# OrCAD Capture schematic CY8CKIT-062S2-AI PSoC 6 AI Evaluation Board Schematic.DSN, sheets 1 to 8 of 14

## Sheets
1 01. Title Page: title: PSoC™ 6 AI Evaluation Board; rev: 03; note: 630-60699-01
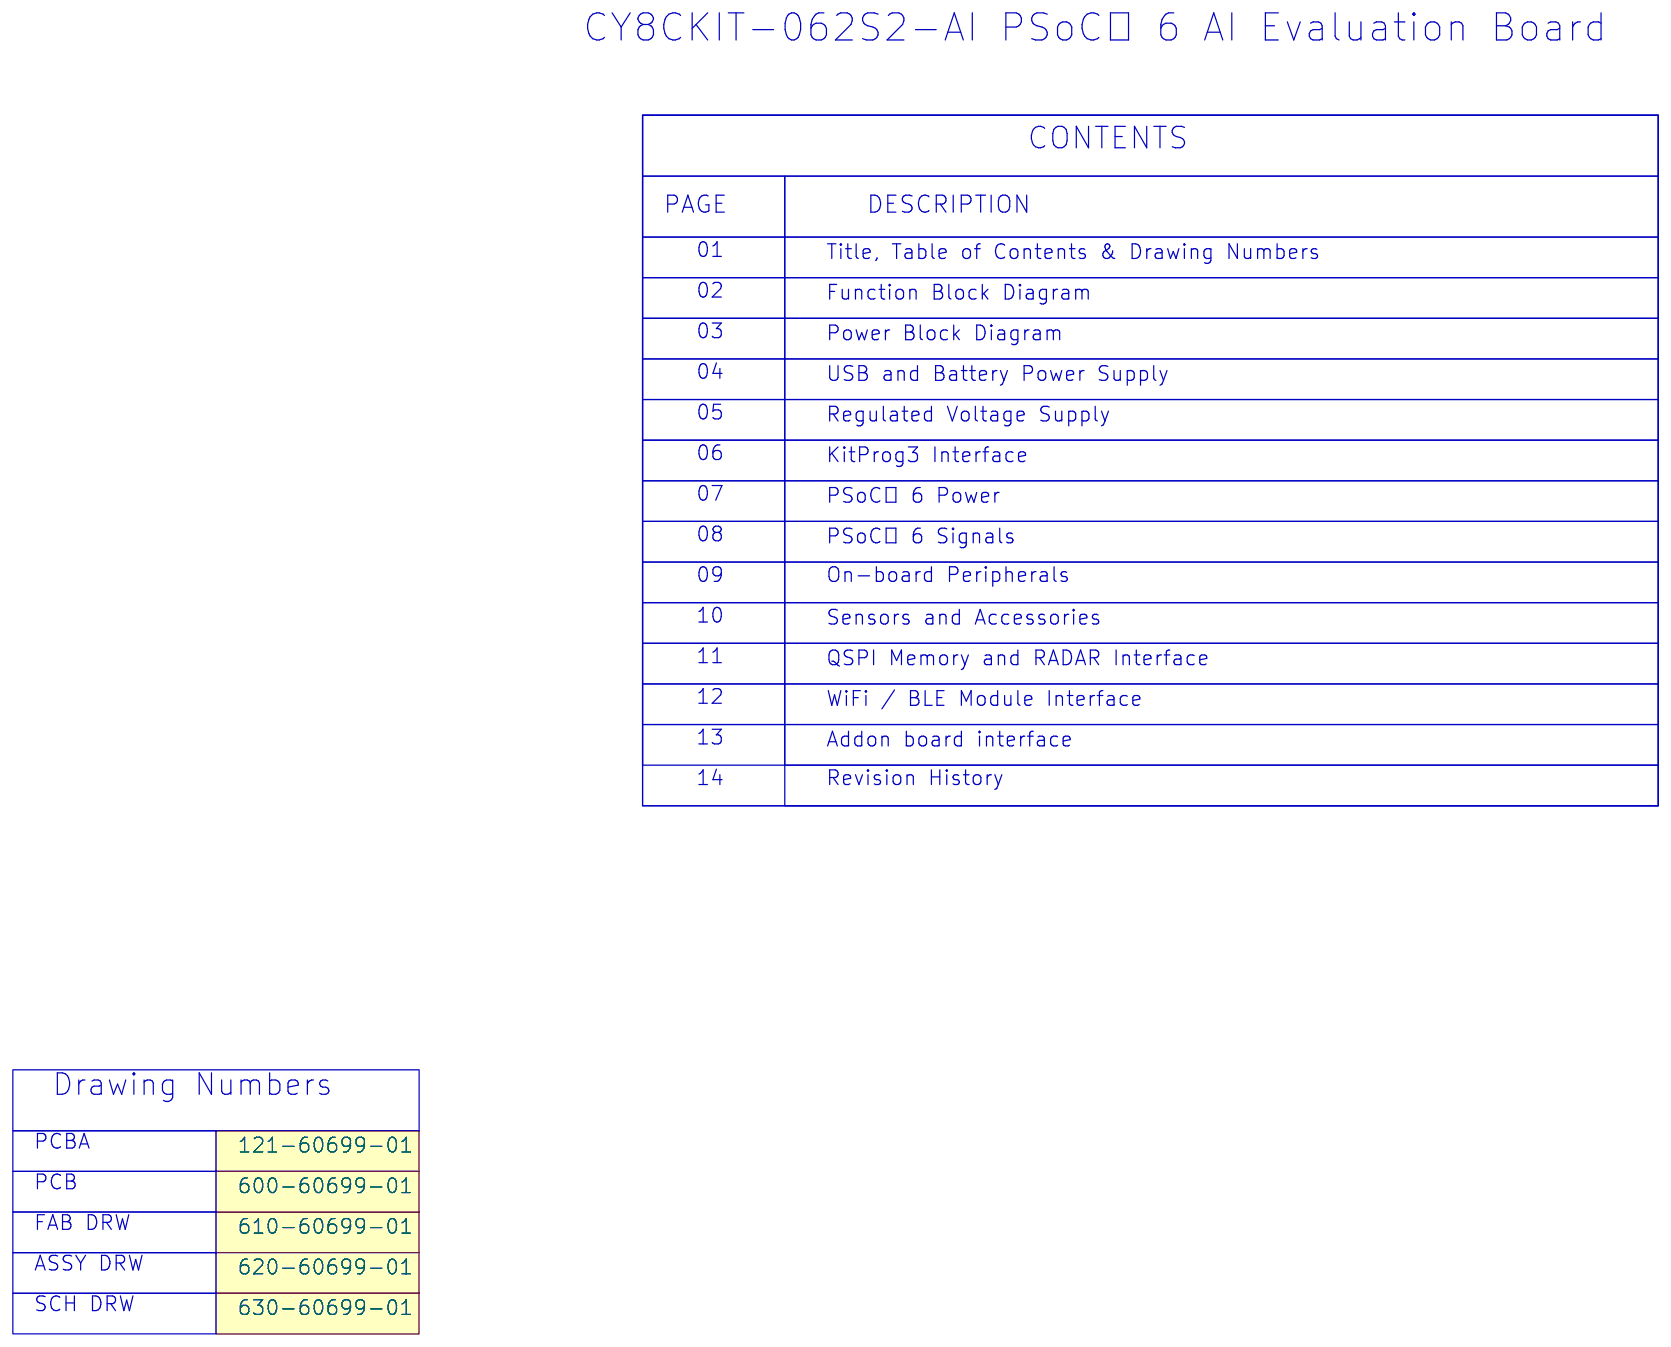
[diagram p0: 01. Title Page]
2 02. Functional Block Diagram
3 03. Power Block Diagram
4 04. USB and Battery Pwr. Supply: size A4
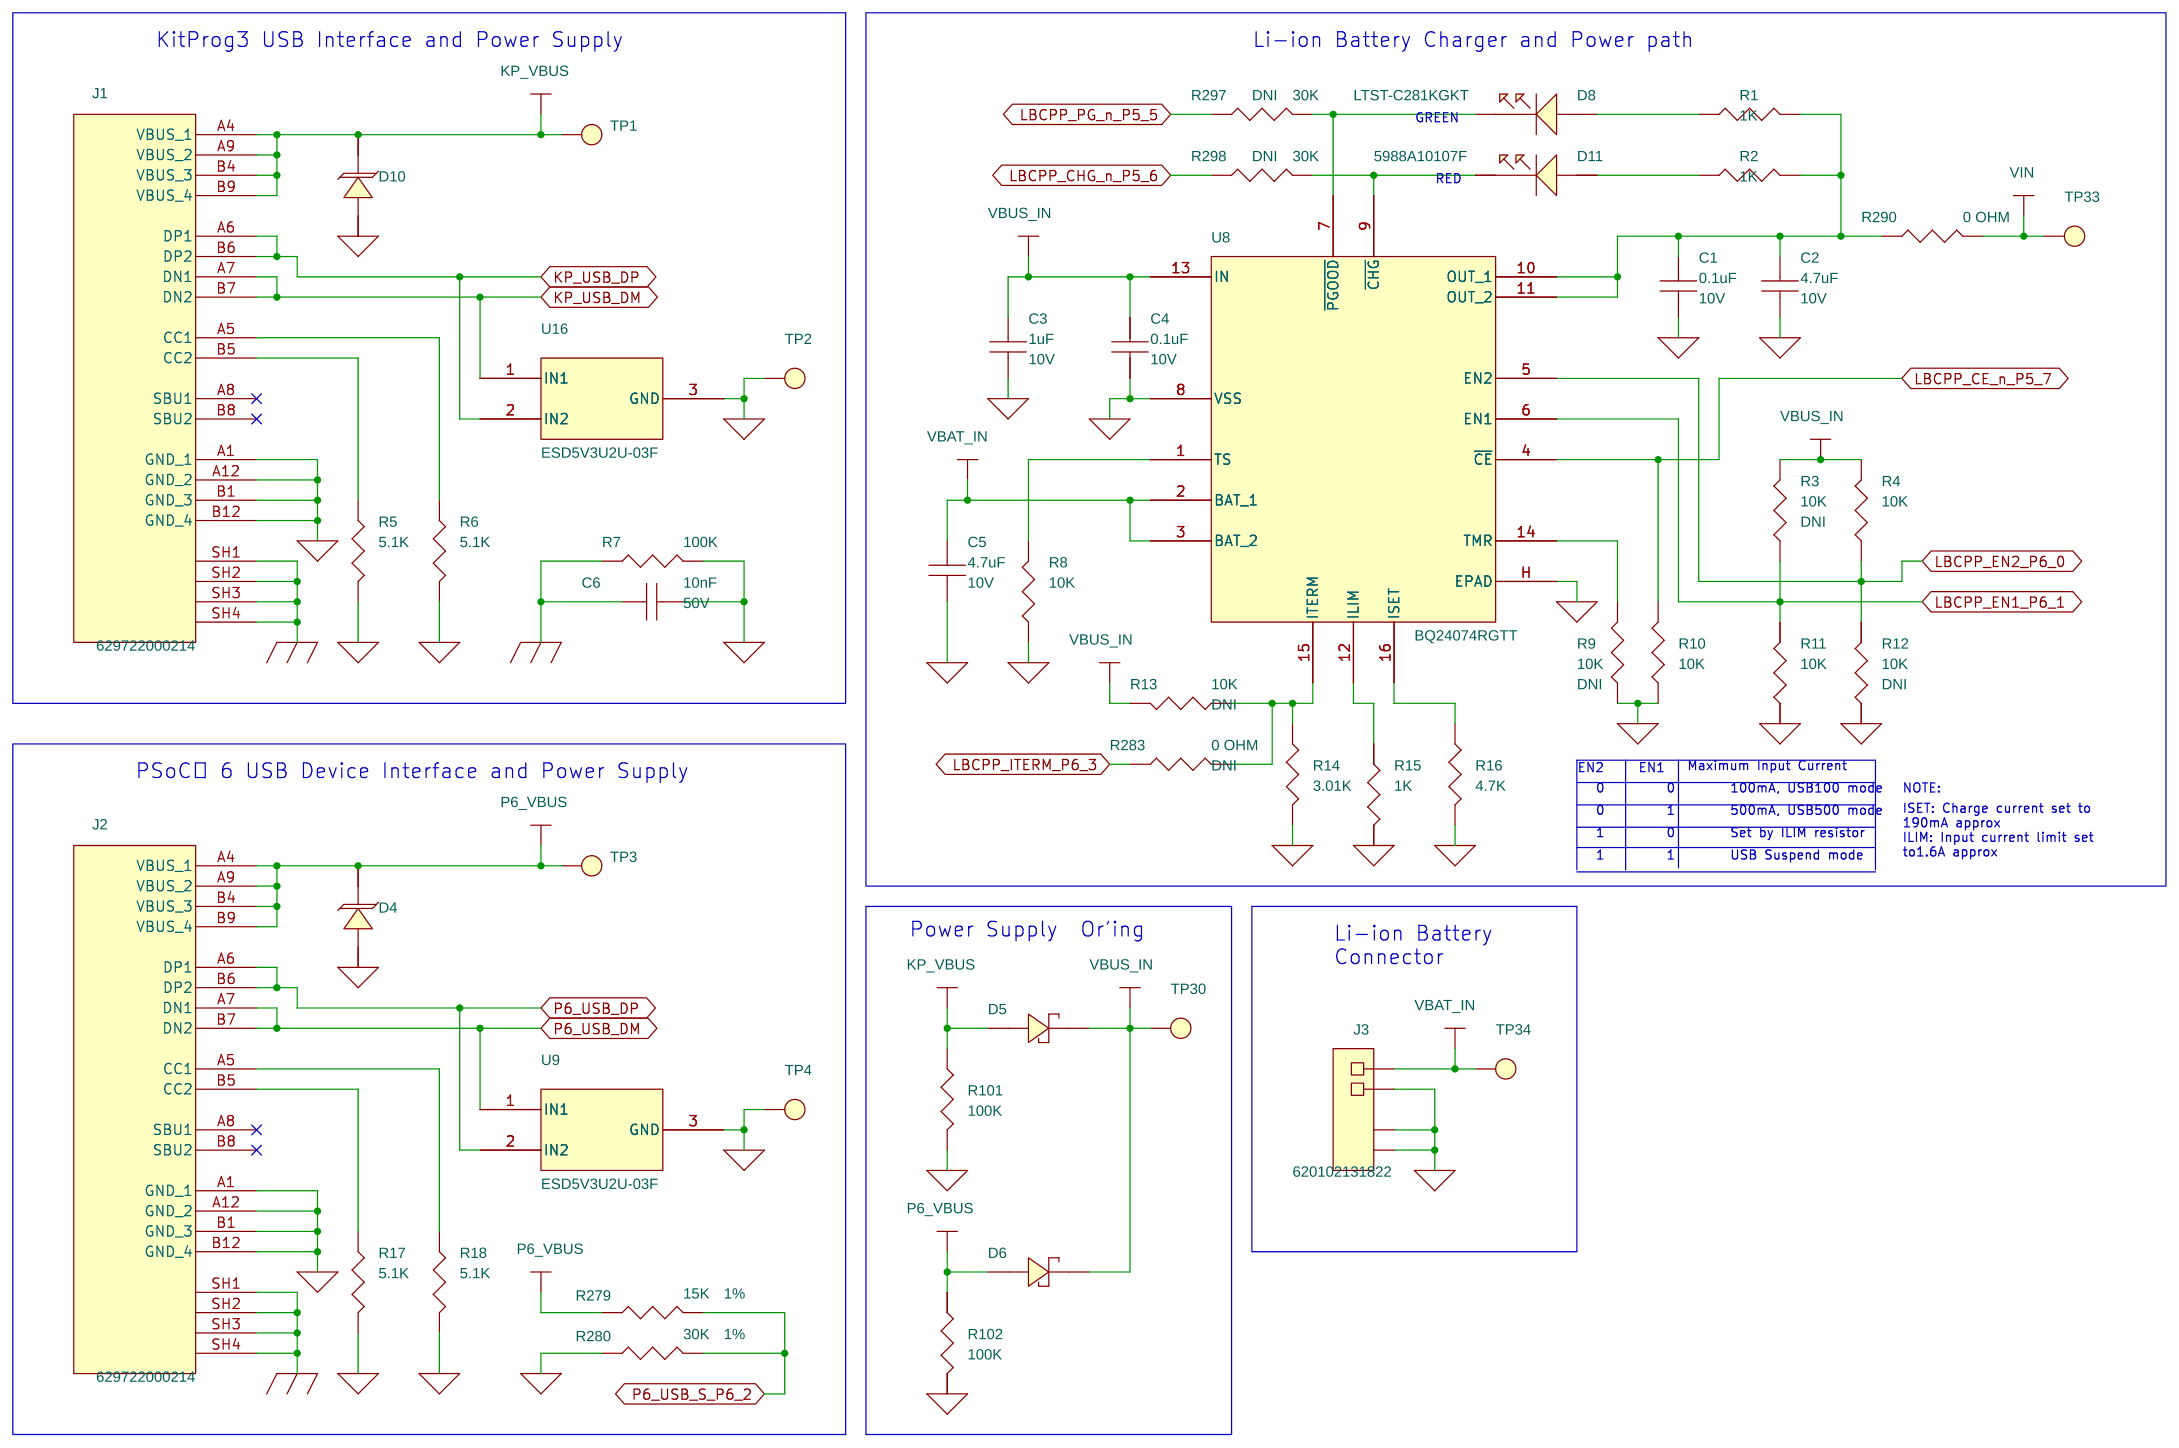
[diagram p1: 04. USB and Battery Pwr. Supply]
5 05. Regulated Voltage Supply: size A4
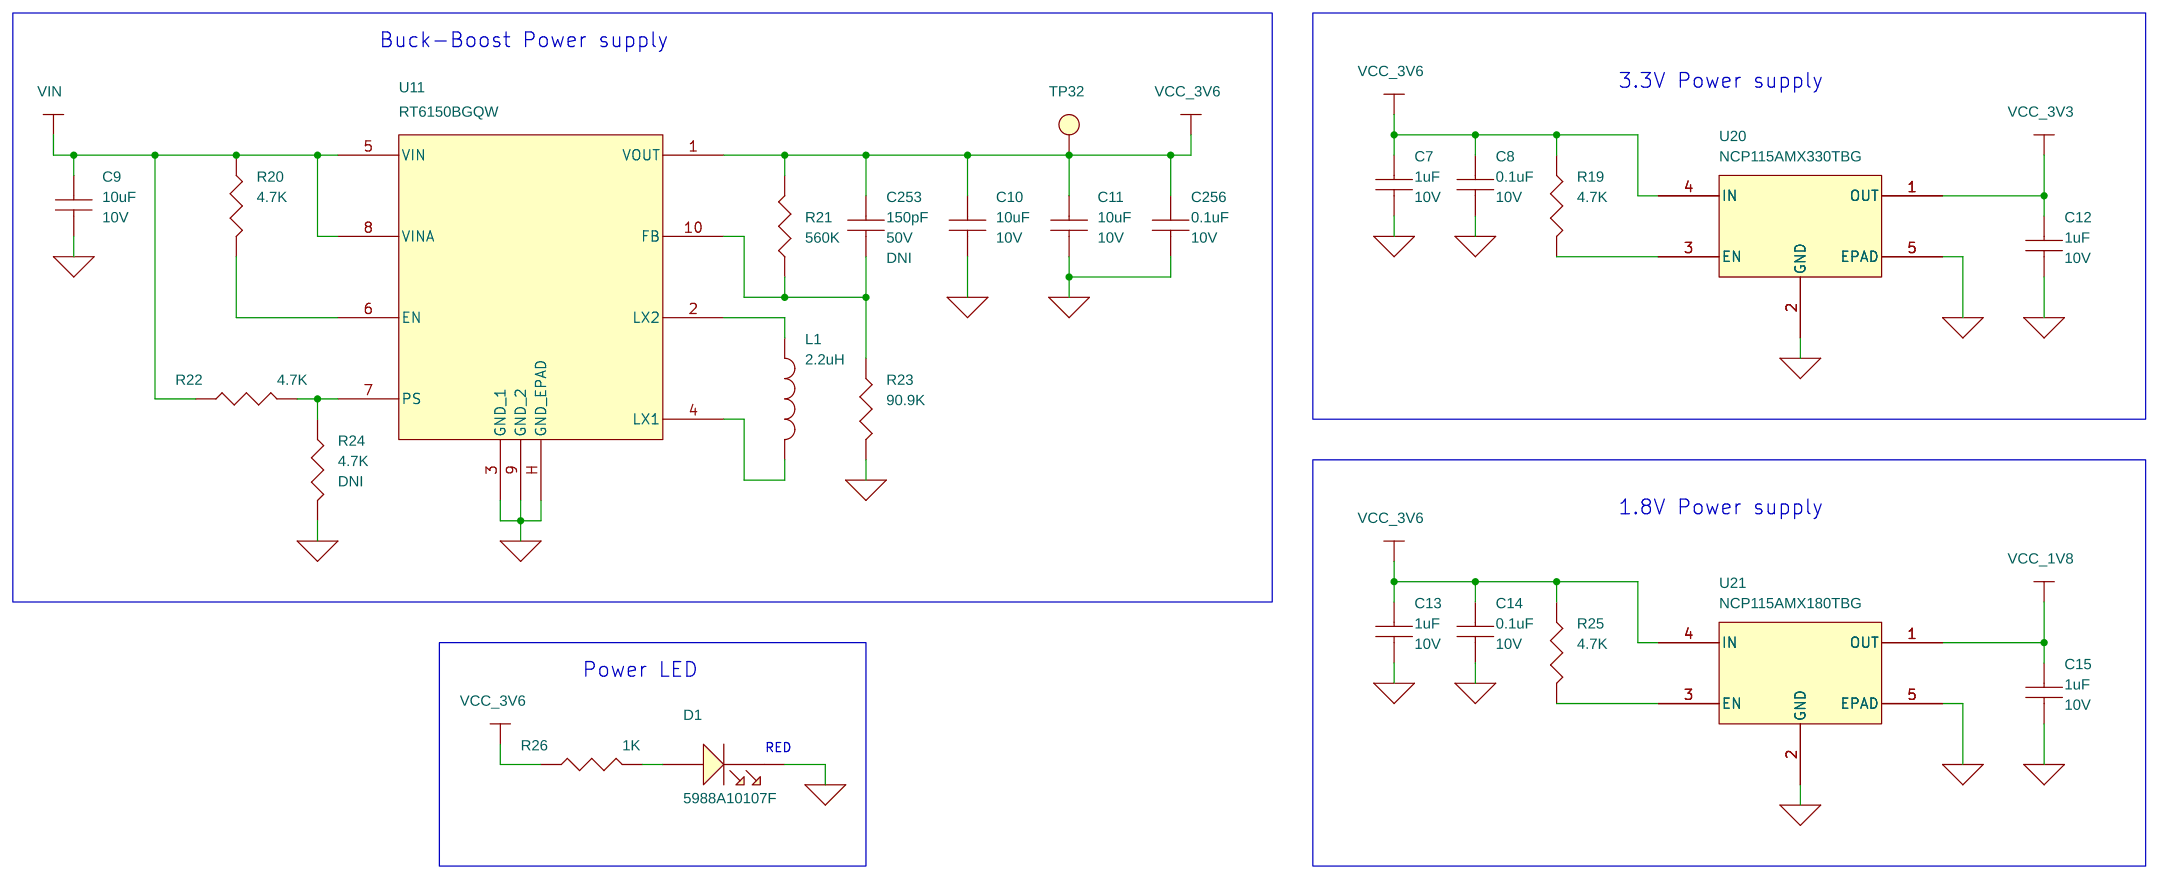
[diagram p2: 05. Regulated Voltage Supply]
6 06. KitProg3 Interface: size A4; note: 630-60682-01
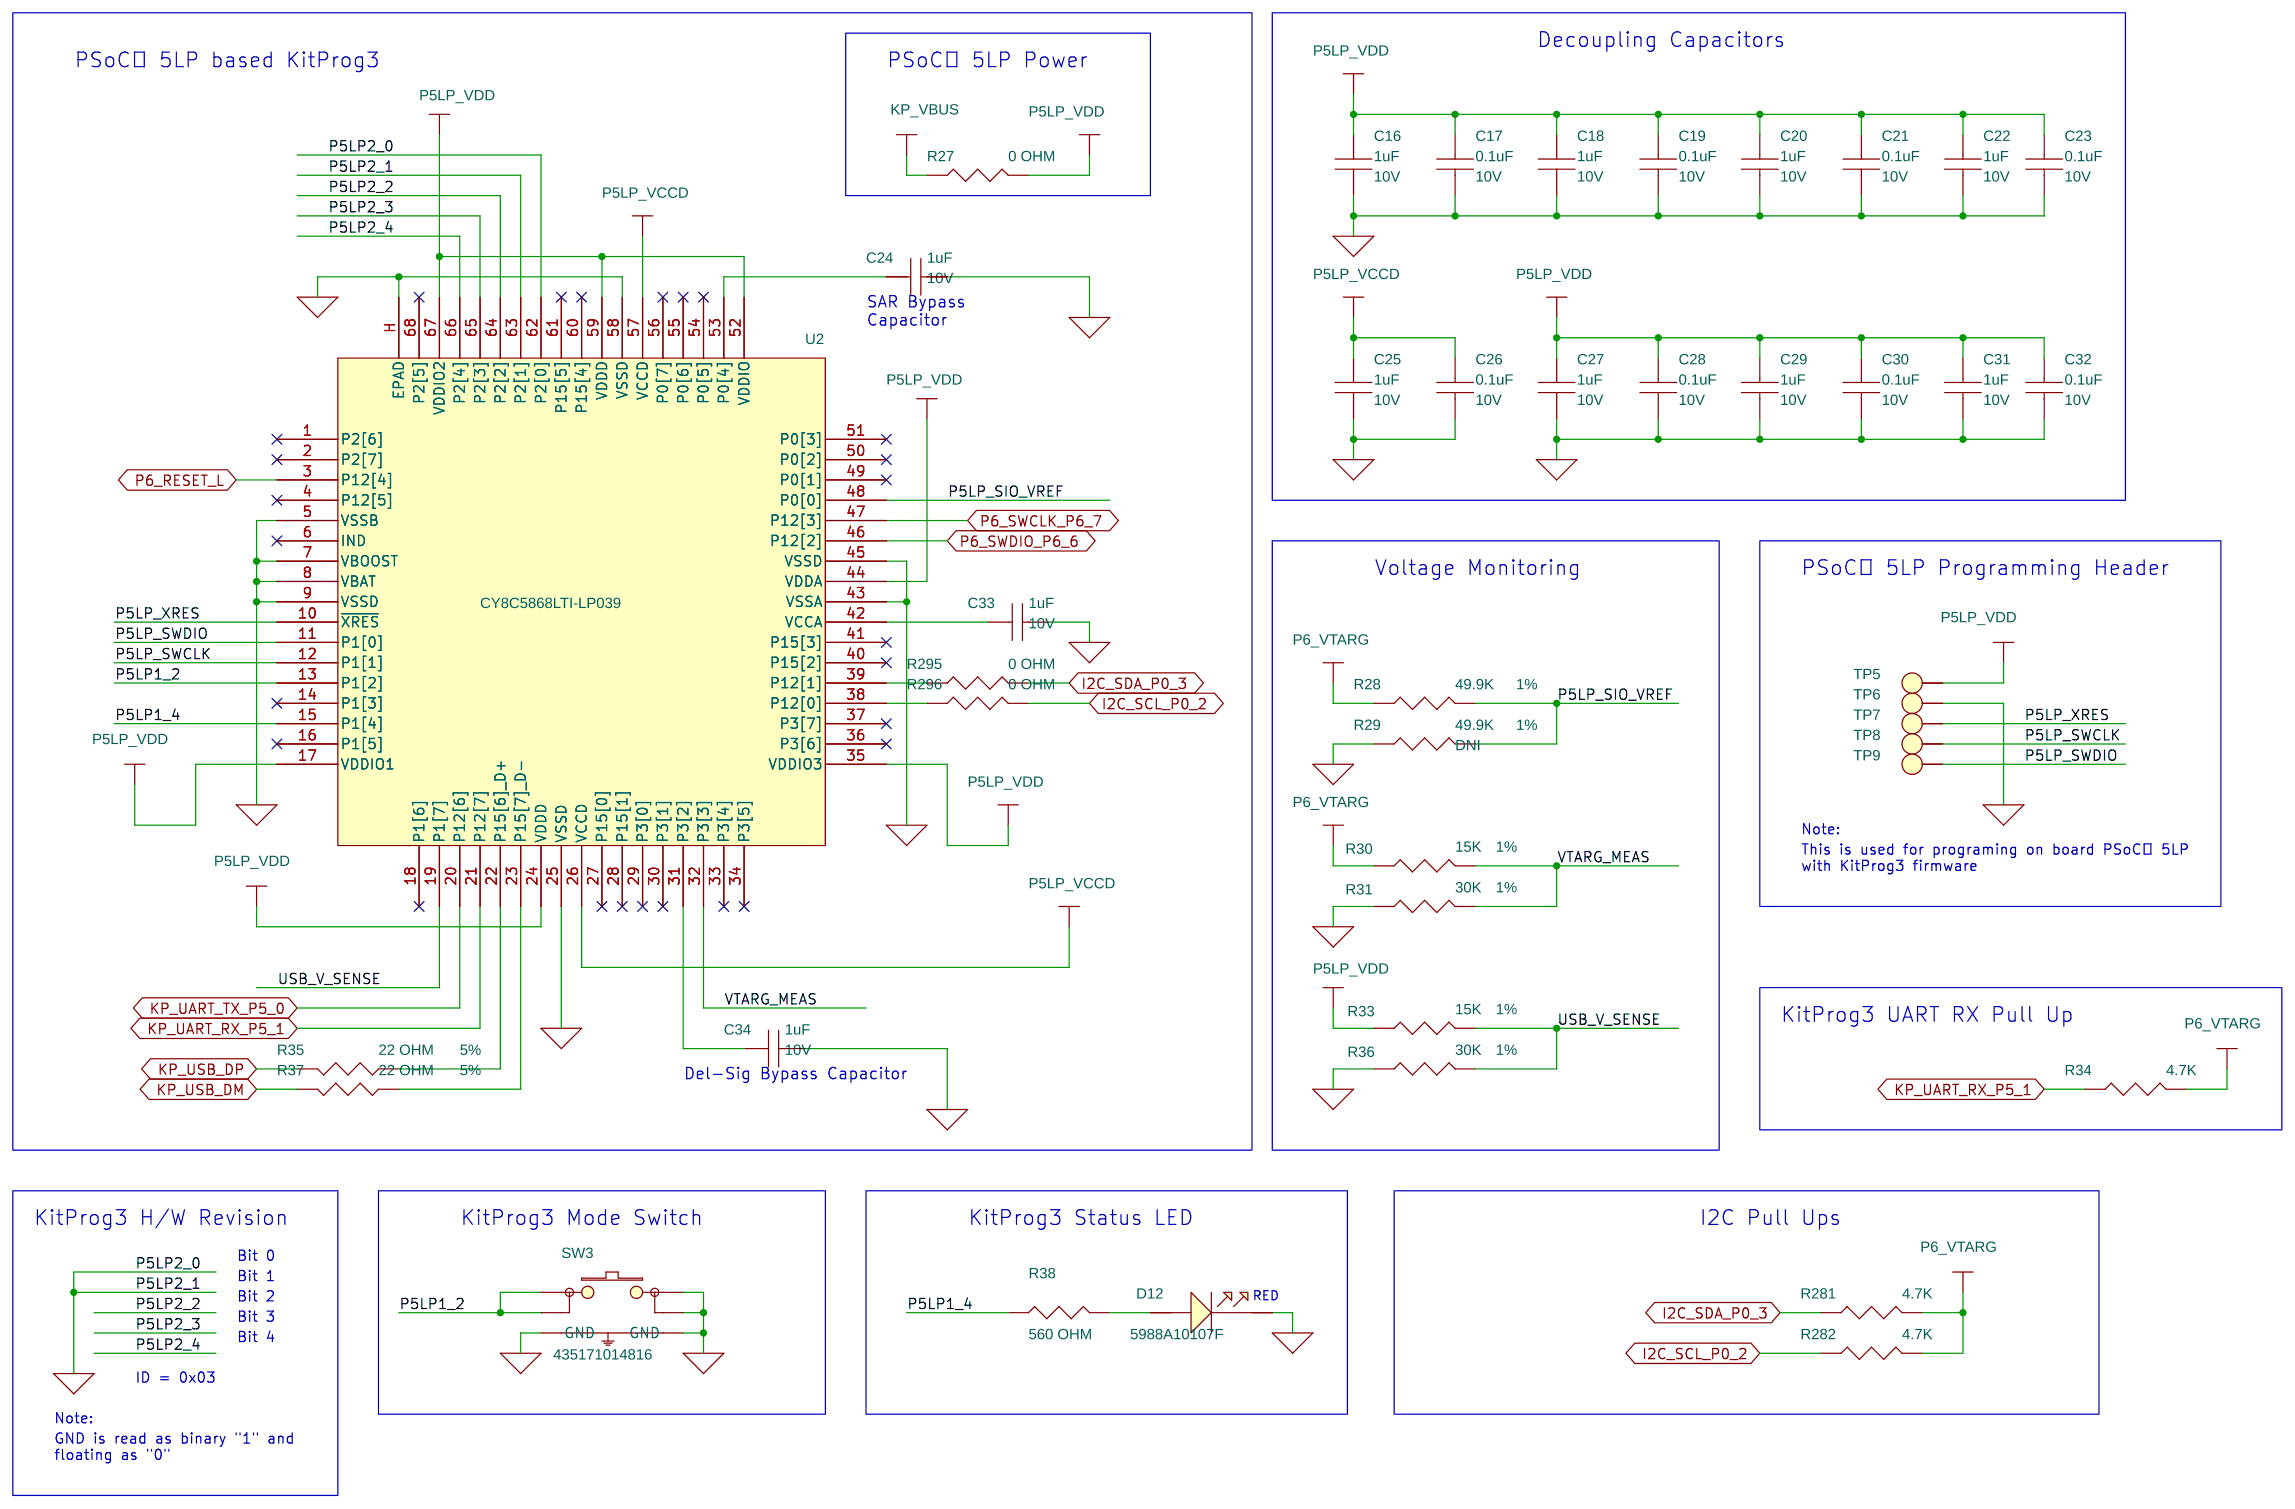
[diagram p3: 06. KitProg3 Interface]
7 10. Sensors and Accesories: size A4
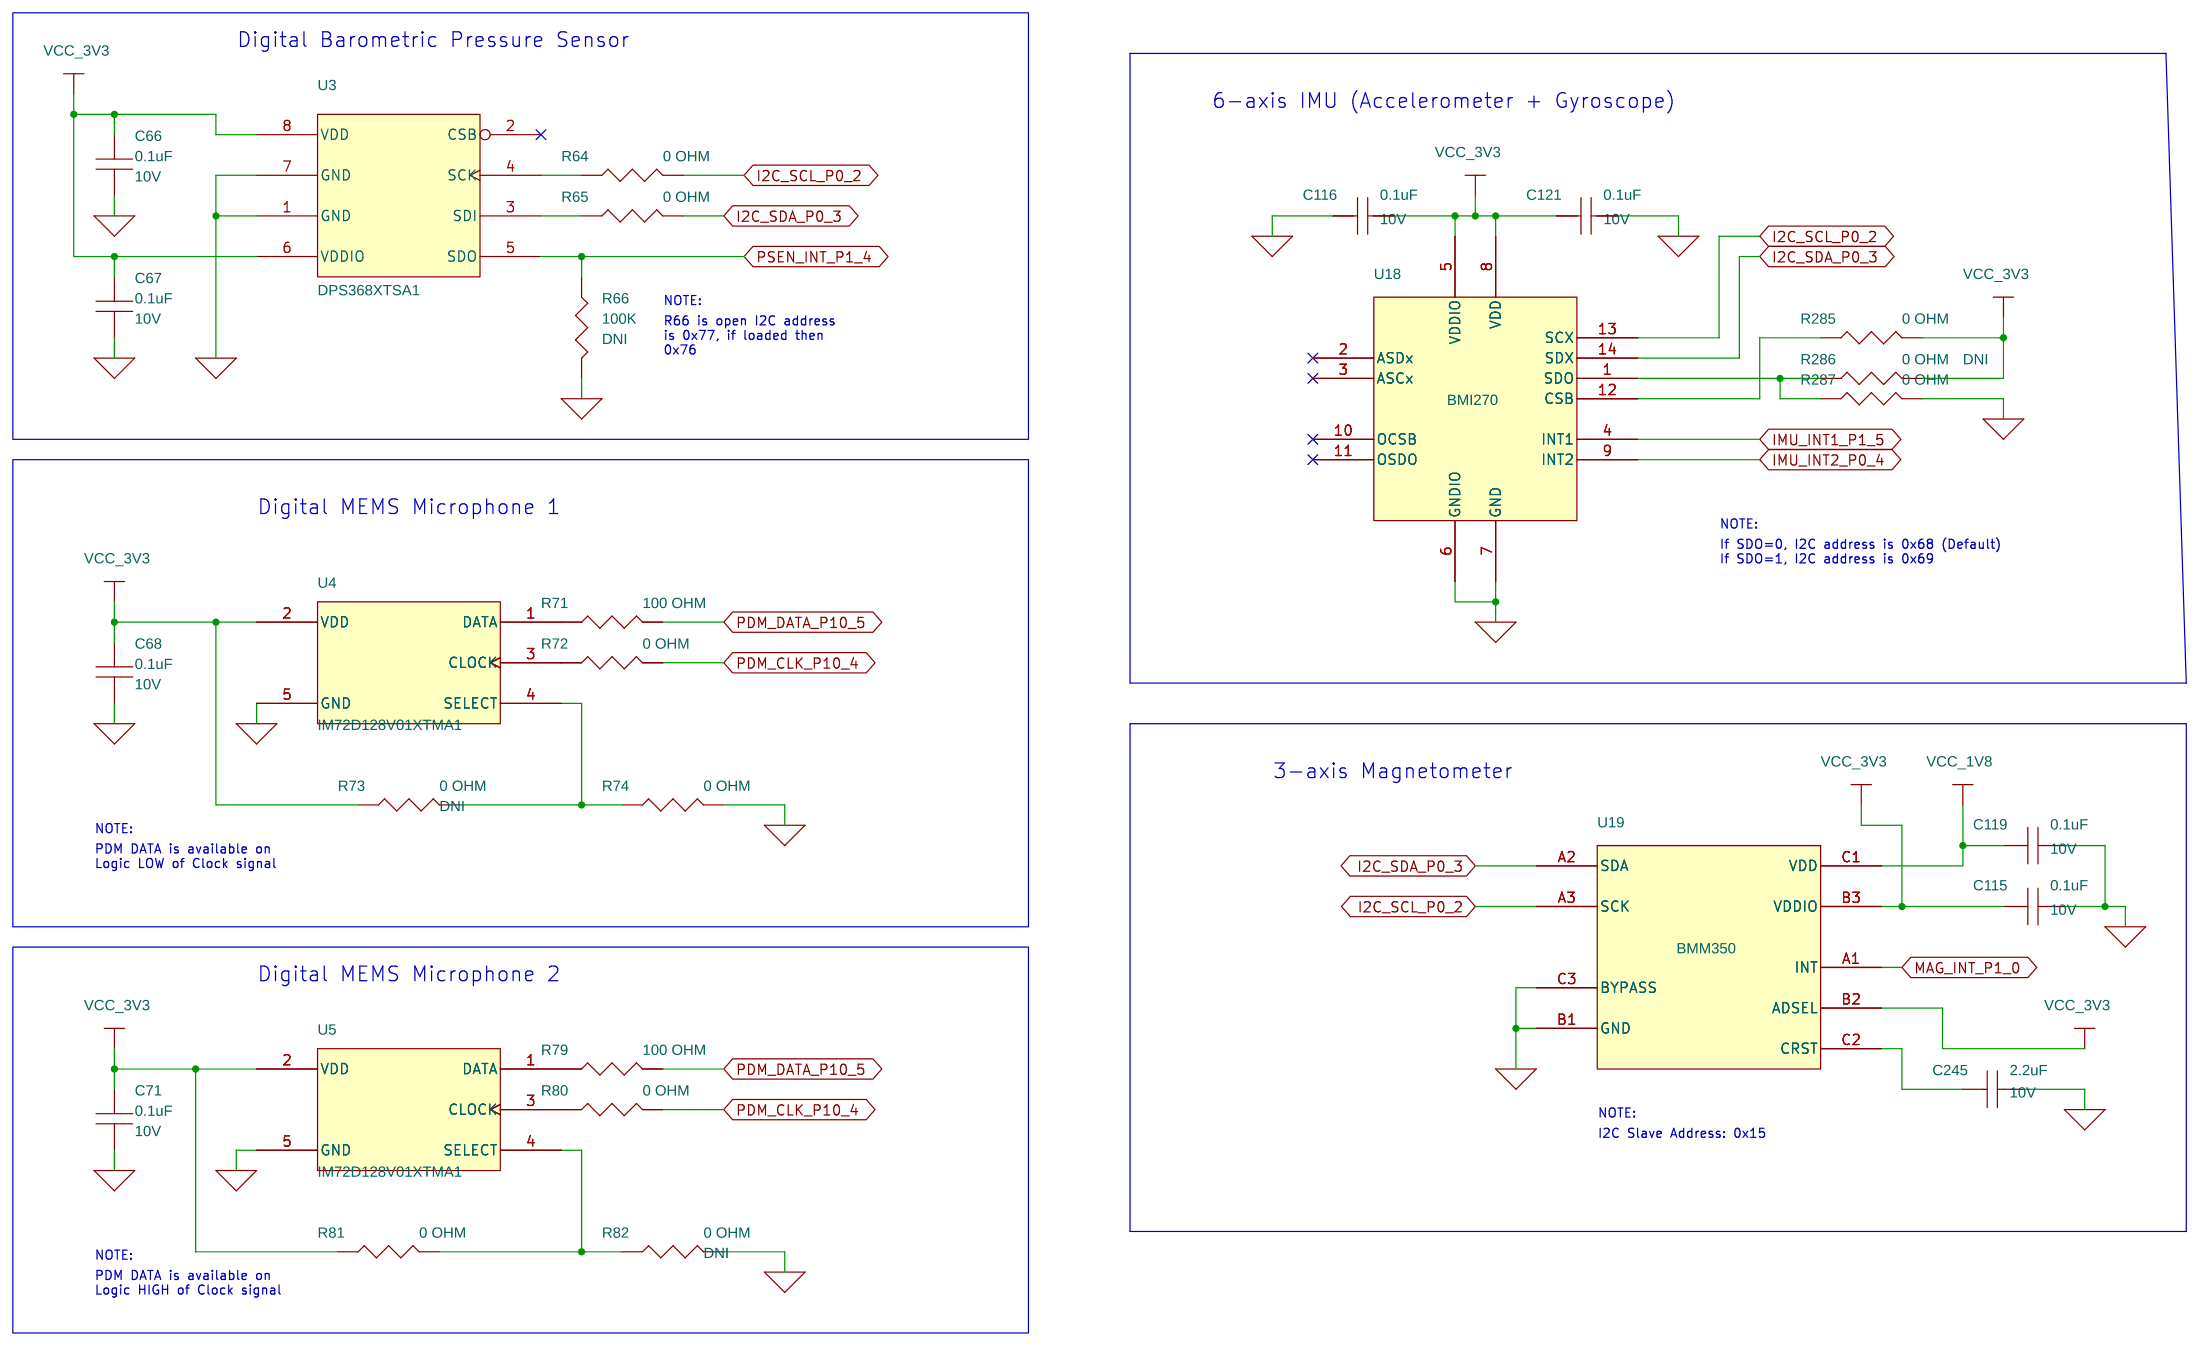
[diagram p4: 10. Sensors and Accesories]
8 09. On-Board Peripherals: size A4
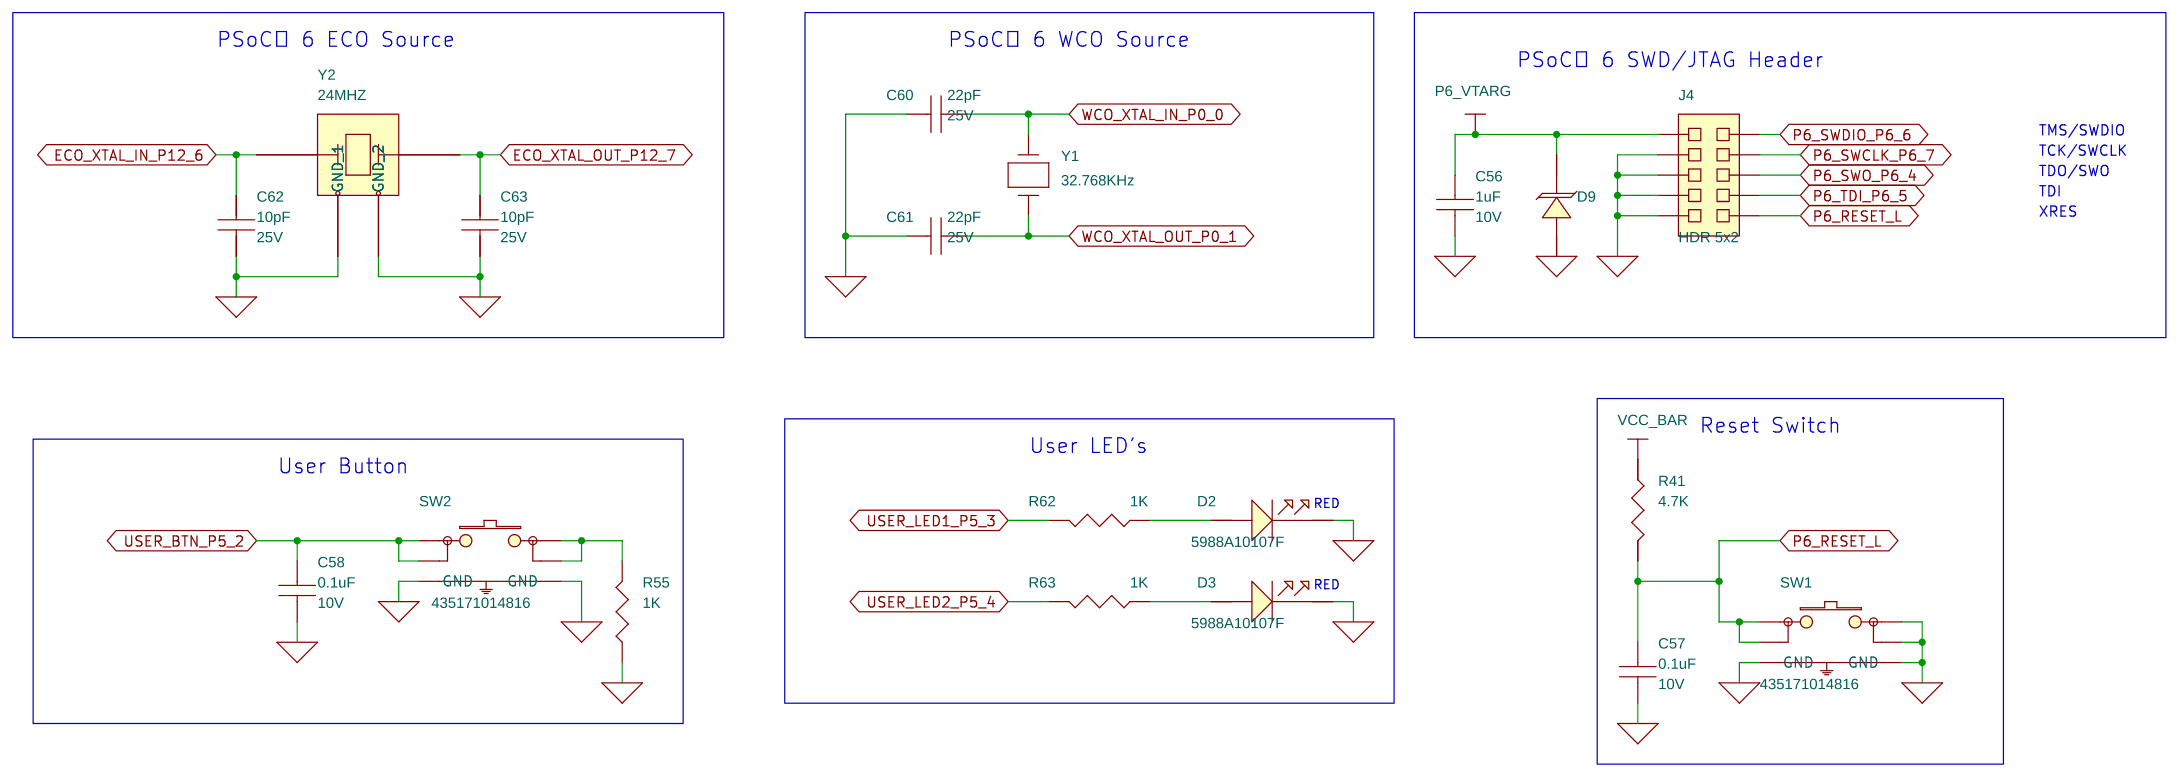
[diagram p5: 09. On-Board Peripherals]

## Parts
sheet 01. Title Page
ACC1  121-60699-01  [TBD]
ACC2  600-60699-01  [TBD]
ACC3  610-60699-01  [TBD]
ACC4  620-60699-01  [TBD]
ACC5  630-60699-01  [TBD]
sheet 04. USB and Battery Pwr. Supply
C1  0.1uF  [CAPC0603_0201N]
C2  4.7uF  [CAPC1005_0402N]
C3  1uF  [CAPC1005_0402N]
C4  0.1uF  [CAPC0603_0201N]
C5  4.7uF  [CAPC1005_0402N]
C6  10nF  [CAPC1005_0402N]
D4  T5V0S5A-7  [SODFL1608X77N]
D5  BAS3010B03WE6327HTSA1  [SOD2512X110N]
D6  BAS3010B03WE6327HTSA1  [SOD2512X110N]
D8  LTST-C281KGKT  [LEDC1005X35N_GN_LITEON]
D10  T5V0S5A-7  [SODFL1608X77N]
D11  5988A10107F  [LEDC1005_0402Q]
J1  629722000214  [GCT_USB4105-GF-A]
J2  629722000214  [GCT_USB4105-GF-A]
J3  620102131822  [JST_S2B-PH-SM4-TB-LF-SN]
R1  1K  [RESC0603_0201N]
R2  1K  [RESC0603_0201N]
R3  10K  [RESC0603_0201N]
R4  10K  [RESC0603_0201N]
R5  5.1K  [RESC0603_0201N]
R6  5.1K  [RESC0603_0201N]
R7  100K  [RESC0603_0201N]
R8  10K  [RESC0603_0201N]
R9  10K  [RESC0603_0201N]
R10  10K  [RESC0603_0201N]
R11  10K  [RESC0603_0201N]
R12  10K  [RESC0603_0201N]
R13  10K  [RESC1005_0402N]
R14  3.01K  [RESC0603_0201N]
R15  1K  [RESC0603_0201N]
R16  4.7K  [RESC0603_0201N]
R17  5.1K  [RESC0603_0201N]
R18  5.1K  [RESC0603_0201N]
R101  100K  [RESC0603_0201N]
R102  100K  [RESC0603_0201N]
R279  15K  [RESC0603_0201N]
R280  30K  [RESC0603_0201N]
R283  0 OHM  [RESC0603_0201N]
R290  0 OHM  [RESC1005_0402N]
R297  30K  [RESC0603_0201N]
R298  30K  [RESC0603_0201N]
TP1  TP_SMD  [tp102c]
TP2  TP_SMD  [tp102c]
TP3  TP_SMD  [tp102c]
TP4  TP_SMD  [tp102c]
TP30  TP_SMD  [tp102c]
TP33  TP_SMD  [tp102c]
TP34  TP_SMD  [tp102c]
U8  BQ24074RGTT  [QFN50P300X300X100-17N_TI]
U9  ESD5V3U2U-03F  [SOTFL40P120X59-3N]
U16  ESD5V3U2U-03F  [SOTFL40P120X59-3N]
sheet 05. Regulated Voltage Supply
C7  1uF  [CAPC1005_0402N]
C8  0.1uF  [CAPC0603_0201N]
C9  10uF  [CAPC1005_0402N]
C10  10uF  [CAPC1005_0402N]
C11  10uF  [CAPC1005_0402N]
C12  1uF  [CAPC1005_0402N]
C13  1uF  [CAPC1005_0402N]
C14  0.1uF  [CAPC0603_0201N]
C15  1uF  [CAPC1005_0402N]
C253  150pF  [CAPC1005_0402N]
C256  0.1uF  [CAPC0603_0201N]
D1  5988A10107F  [LEDC1005_0402Q]
L1  2.2uH  [IND_NR3015T2R2M]
R19  4.7K  [RESC0603_0201N]
R20  4.7K  [RESC0603_0201N]
R21  560K  [RESC0603_0201N]
R22  4.7K  [RESC0603_0201N]
R23  90.9K  [RESC0603_0201N]
R24  4.7K  [RESC0603_0201N]
R25  4.7K  [RESC0603_0201N]
R26  1K  [RESC0603_0201N]
TP32  TP_SMD  [tp102c]
U11  RT6150BGQW  [DFN50P250X250X80-11N]
U20  NCP115AMX330TBG  [DFN65P100X100X43-5N]
U21  NCP115AMX180TBG  [DFN65P100X100X43-5N]
sheet 06. KitProg3 Interface
C16  1uF  [CAPC0603_0201N]
C17  0.1uF  [CAPC0603_0201N]
C18  1uF  [CAPC0603_0201N]
C19  0.1uF  [CAPC0603_0201N]
C20  1uF  [CAPC0603_0201N]
C21  0.1uF  [CAPC0603_0201N]
C22  1uF  [CAPC0603_0201N]
C23  0.1uF  [CAPC0603_0201N]
C24  1uF  [CAPC0603_0201N]
C25  1uF  [CAPC0603_0201N]
C26  0.1uF  [CAPC0603_0201N]
C27  1uF  [CAPC0603_0201N]
C28  0.1uF  [CAPC0603_0201N]
C29  1uF  [CAPC0603_0201N]
C30  0.1uF  [CAPC0603_0201N]
C31  1uF  [CAPC0603_0201N]
C32  0.1uF  [CAPC0603_0201N]
C33  1uF  [CAPC0603_0201N]
C34  1uF  [CAPC0603_0201N]
D12  5988A10107F  [LEDC1005_0402Q]
R27  0 OHM  [RESC1005_0402N]
R28  49.9K  [RESC0603_0201N]
R29  49.9K  [RESC0603_0201N]
R30  15K  [RESC0603_0201N]
R31  30K  [RESC0603_0201N]
R33  15K  [RESC0603_0201N]
R34  4.7K  [RESC0603_0201N]
R35  22 OHM  [RESC0603_0201N]
R36  30K  [RESC0603_0201N]
R37  22 OHM  [RESC0603_0201N]
R38  560 OHM  [RESC0603_0201N]
R281  4.7K  [RESC0603_0201N]
R282  4.7K  [RESC0603_0201N]
R295  0 OHM  [RESC0603_0201N]
R296  0 OHM  [RESC0603_0201N]
SW3  435171014816  [SW_435171014816]
TP5  TP_SMD  [tp102c]
TP6  TP_SMD  [tp102c]
TP7  TP_SMD  [tp102c]
TP8  TP_SMD  [tp102c]
TP9  TP_SMD  [tp102c]
U2  CY8C5868LTI-LP039  [QFN40P800X800_68-H580N]
sheet 09. On-Board Peripherals
C56  1uF  [CAPC0603_0201N]
C57  0.1uF  [CAPC0603_0201N]
C58  0.1uF  [CAPC0603_0201N]
C60  22pF  [CAPC0603_0201N]
C61  22pF  [CAPC0603_0201N]
C62  10pF  [CAPC0603_0201N]
C63  10pF  [CAPC0603_0201N]
D2  5988A10107F  [LEDC1005_0402Q]
D3  5988A10107F  [LEDC1005_0402Q]
D9  ESD5V0D5-TP  [SODFL1608X77N]
J4  HDR 5x2  [SAMT_FTSH-105-XX-X-DV-K]
R41  4.7K  [RESC0603_0201N]
R55  1K  [RESC0603_0201N]
R62  1K  [RESC0603_0201N]
R63  1K  [RESC0603_0201N]
SW1  435171014816  [SW_435171014816]
SW2  435171014816  [SW_435171014816]
Y1  32.768KHz  [XTAL_ABS05_1M6X1M]
Y2  24MHZ  [OSCCC205X165X60-4N]
sheet 10. Sensors and Accesories
C66  0.1uF  [CAPC0603_0201N]
C67  0.1uF  [CAPC0603_0201N]
C68  0.1uF  [CAPC0603_0201N]
C71  0.1uF  [CAPC0603_0201N]
C115  0.1uF  [CAPC0603_0201N]
C116  0.1uF  [CAPC0603_0201N]
C119  0.1uF  [CAPC0603_0201N]
C121  0.1uF  [CAPC0603_0201N]
C245  2.2uF  [CAPC1005_0402N]
R64  0 OHM  [RESC0603_0201N]
R65  0 OHM  [RESC0603_0201N]
R66  100K  [RESC0603_0201N]
R71  100 OHM  [RESC0603_0201N]
R72  0 OHM  [RESC0603_0201N]
R73  0 OHM  [RESC0603_0201N]
R74  0 OHM  [RESC0603_0201N]
R79  100 OHM  [RESC0603_0201N]
R80  0 OHM  [RESC0603_0201N]
R81  0 OHM  [RESC0603_0201N]
R82  0 OHM  [RESC0603_0201N]
R285  0 OHM  [RESC0603_0201N]
R286  0 OHM  [RESC0603_0201N]
R287  0 OHM  [RESC0603_0201N]
U3  DPS368XTSA1  [LGA8S145X65P2X4_200X250X110]
U4  IM72D128V01XTMA1  [MIC_IM73A135V01XTSA1]
U5  IM72D128V01XTMA1  [MIC_IM73A135V01XTSA1]
U18  BMI270  [BOSCH_BMI323]
U19  BMM350  [BOSCH_BMM350]

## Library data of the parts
ACC1 = PCB: ASSY, PCBA, CY8CKIT-062S2-AI - PSoC6 AI Evluation board; Dist_Part_Number: -NA-; Distributor: -NA-; Manufacturer: Cypress Approved CM; Mfr_Name: Cypress Approved CM; Sub_Allowed: NO
ACC2 = PCB: PCB, BARE, CY8CKIT-062S2-AI - PSoC6 AI Evluation board; Dist_Part_Number: -NA-; Distributor: -NA-; Manufacturer: Cypress Approved CM; Mfr_Name: Cypress Approved CM; Sub_Allowed: NO
ACC3 = PCB: DRW, FABRICATION DRAWING, CY8CKIT-062S2-AI - PSoC6 AI Evluation board; Dist_Part_Number: -NA-; Distributor: -NA-; Manufacturer: -NA-; Mfr_Name: -NA-; Sub_Allowed: NO
ACC4 = PCB: DRW, ASSEMBLY DRAWING, CY8CKIT-062S2-AI - PSoC6 AI Evluation board; Dist_Part_Number: -NA-; Distributor: -NA-; Manufacturer: -NA-; Mfr_Name: -NA-; Sub_Allowed: NO
ACC5 = PCB: DRW, SCHEMATIC DRAWING, CY8CKIT-062S2-AI - PSoC6 AI Evluation board; Dist_Part_Number: -NA-; Distributor: -NA-; Manufacturer: -NA-; Mfr_Name: -NA-; Sub_Allowed: NO
C1 C4 C8 C14 C66-C68 C71 C115 C116 C119 C121 C256 = CAP-NP: CAP, CER, 0.1uF, 20%, X5R, 10V, 0201; Approved: Approved; CY_PN: 510-60777-01; Device_File: 510-60777-01; Dielectric: X5R; FPLIST: CAPC0603_0201N,CAPC0603_0201Q; Lifecycle: Active; Manufacturer: Wurth; Manufacturer_PN: 885012104002; Operating_Temp: -55°C ~ 85°C; Package: 0201; Part_Status: In Prod; Tolerance: 20%; Voltage: 10V
C2 C5 = CAP-NP: CAP, CER, 0402, 4.7uF, 20%, 10V, X5R; Approved: Approved; CY_PN: 510-60422-01; Device_File: 510-60422-01; Dielectric: X5R; FPLIST: CAPC1005_0402N,CAPC1005_0402M,capc1005_is0402q; Lifecycle: Active; Manufacturer: Murata; Manufacturer_PN: GRM155R61A475MEAAD; Operating_Temp: -55°C ~ 85°C; Package: 0402; Part_Status: Unrel; Tolerance: 20%; Voltage: 10V
C3 C7 C12 C13 C15 = CAP-NP: CAP, CER, 1UF, 20%, 10V, X5R, 0402; Approved: Approved; CY_PN: 510-60877-01; Device_File: 510-60877-01; Dielectric: X5R; FPLIST: CAPC1005_0402N,CAPC1005_0402M; Lifecycle: Active; Manufacturer: Wurth; Manufacturer_PN: 885012105012; Operating_Temp: -55°C ~ 85°C; Package: 0402; Part_Status: In Prod; Tolerance: 20%; Voltage: 10V
C6 = CAP-NP: CAP, CER, 10nF, 10%, X7R, 50V, 0402; Approved: Approved; CY_PN: 510-60089-01; Device_File: 510-60089-01; Dielectric: X7R; FPLIST: CAPC1005_0402N,CAPC1005_0402M; Lifecycle: Active; Manufacturer: Wurth; Manufacturer_PN: 885012205067; Operating_Temp: - 55 C to + 125 C; Package: 0402; Part_Status: In Prod; Tolerance: 10%; Voltage: 50V
D4 D10 = DIO-TVS: DIODE, TVS, 17.3V, 15A, SOD-523; Approved: Approved; CY_PN: 530-60314-01; Device_File: 530-60314-01; Lifecycle: Active; Manufacturer: Diodes Incorporated; Operating_Temp: -65°C ~ 150°C; Package: SOD-523; Part_Status: Unrel; Rating: 15A; Voltage: 17.3V
D5 D6 = DIO-SCHOTTKY: DIODE SCHOTTKY 30V 1A SOD323-2; Approved: Approved; Lifecycle: Active; Manufacturer: Infineon; Operating_Temp: -65°C ~ 125°C; Package: SOD323-2; Part_Status: Unrel; Rating: 1A; Voltage: 30V
D8 = DIO-LED: LED, GREEN, CLEAR, 571nm, 2V, 0402; Approved: Approved; CY_PN: 534-60149-01; Device_File: 534-60149-01; Lifecycle: Active; Manufacturer: Lite-On Inc.; Operating_Temp: -30°C to 85°C; Package: 0402; Part_Status: Unrel; Rating: 20mA; Voltage: 2V
D1-D3 D11 D12 = DIO-LED: DIO, LED, 635nm, RED, 0402; Approved: Approved; CY_PN: 534-60141-01; Device_File: 534-60141-01; Lifecycle: Active; Manufacturer: Dialight; Operating_Temp: -40°C ~ 85°C; Package: 0402; Part_Status: Unrel; Rating: 5mA; Voltage: 1.6V
J1 J2 = USB_TYPE_C-16PIN_4SH: CONN, RCPT, USB, TYPE-C, USB2.0, 12POS, TOP MOUNT, RA, SMD; Approved: Approved; CY_PN: 720-60675-01; Conatct_Length: NA; Contact_Finish: GOLD; Current_Rating: 5A; Device_File: 720-60675-01; Lifecycle: Active; Manufacturer: Wurth; Mated_Height: NA; Operating_Temp: -40°C to +85°C; Part_Status: In Prod; Pin_Pitch: NA; Pins: 12; Row_pitch: NA; Rows: 1; Shrouding: NA
J3 = PLG-2-J_SH1_2: CONN, HDR, 1x2POS, SHROUNDED, R/A, 2MM PITCH, SMT; Approved: Approved; CY_PN: 720-60595-01; Conatct_Length: NA; Contact_Finish: Tin; Current_Rating: 2A; Device_File: 720-60595-01; Lifecycle: Active; Manufacturer: Wurth; Mated_Height: NA; Operating_Temp: -40°C ~ 85°C; Part_Status: In Des; Pin_Pitch: 2mm; Pins: 2; Row_pitch: NA; Rows: 1; Shrouding: Shrouded
R1 R2 R15 R26 R55 R62 R63 = RES: RES, 1K OHM, 1%, 1/20W, 0201; Approved: Approved; CY_PN: 500-61336-01; Device_File: 500-61336-01; FPLIST: RESC0603_0201N,RESC0603_0201Q; Lifecycle: Active; Manufacturer: Yageo; Manufacturer_PN: RC0201FR-071KL; Operating_Temp: -55°C ~ 125°C; Package: 0201; Part_Status: Unrel; Rating: 1/20W; Tolerance: 1%
R3 R9 = RES: RES, 10K OHM, 1%, 1/20W, 0201; Approved: Approved; CY_PN: 500-61335-01; DNI: DNI; Device_File: 500-61335-01; FPLIST: RESC0603_0201N,RESC0603_0201Q; Lifecycle: Active; Manufacturer: Yageo; Manufacturer_PN: RC0201FR-0710KL; Operating_Temp: -55°C ~ 125°C; Package: 0201; Part_Status: Unrel; Rating: 1/20W; Tolerance: 1%
R4 = RES: RES, 10K OHM, 1%, 1/20W, 0201; Approved: Approved; CY_PN: 500-61335-01; Device_File: 500-61335-01; FPLIST: RESC0603_0201N,RESC0603_0201Q; Lifecycle: Active; Manufacturer: Yageo; Manufacturer_PN: RC0201FR-0710KL; NO_XNET_CONNECTION: YES; Operating_Temp: -55°C ~ 125°C; Package: 0201; Part_Status: Unrel; Rating: 1/20W; Tolerance: 1%
R5 R6 R17 R18 = RES: RES, 5.1K OHM, 5%, 1/20W, 0201; Approved: Approved; CY_PN: 500-61333-01; Device_File: 500-61333-01; FPLIST: RESC0603_0201N,RESC0603_0201Q; Lifecycle: Active; Manufacturer: Yageo; Manufacturer_PN: RC0201JR-075K1L; Operating_Temp: -55°C ~ 125°C; Package: 0201; Part_Status: Unrel; Rating: 1/20W; Tolerance: 5%
R7 R101 R102 = RES: RES, 100K OHM, 1%, 1/20W, 0201; Approved: Approved; CY_PN: 500-61334-01; Device_File: 500-61334-01; FPLIST: RESC0603_0201N,RESC0603_0201Q; Lifecycle: Active; Manufacturer: Yageo; Manufacturer_PN: RC0201FR-07100KL; Operating_Temp: -55°C ~ 125°C; Package: 0201; Part_Status: Unrel; Rating: 1/20W; Tolerance: 1%
R8 R10 R11 = RES: RES, 10K OHM, 1%, 1/20W, 0201; Approved: Approved; CY_PN: 500-61335-01; Device_File: 500-61335-01; FPLIST: RESC0603_0201N,RESC0603_0201Q; Lifecycle: Active; Manufacturer: Yageo; Manufacturer_PN: RC0201FR-0710KL; Operating_Temp: -55°C ~ 125°C; Package: 0201; Part_Status: Unrel; Rating: 1/20W; Tolerance: 1%
R12 = RES: RES, 10K OHM, 1%, 1/20W, 0201; Approved: Approved; CY_PN: 500-61335-01; DNI: DNI; Device_File: 500-61335-01; FPLIST: RESC0603_0201N,RESC0603_0201Q; Lifecycle: Active; Manufacturer: Yageo; Manufacturer_PN: RC0201FR-0710KL; NO_XNET_CONNECTION: YES; Operating_Temp: -55°C ~ 125°C; Package: 0201; Part_Status: Unrel; Rating: 1/20W; Tolerance: 1%
R13 = RES: RES, Fixed, 10K, 1%, 1/16W, 0402; CY_PN: 500-61080-01; DNI: DNI; Device_File: 500-61080-01; FPLIST: RESC1005_0402N,RESC1005_0402M; Lifecycle: Active; Manufacturer: Yageo; Manufacturer_PN: RT0402FRE0710KL; NO_XNET_CONNECTION: YES; Operating_Temp: -55°C to 155°C; Package: 0402; Part_Status: In Production; Rating: 1/16W
R14 = RES: RES, 3.01K OHM, 1%, 1/20W, 0201; Approved: Approved; CY_PN: 500-61337-01; Device_File: 500-61337-01; FPLIST: RESC0603_0201N,RESC0603_0201Q; Lifecycle: Active; Manufacturer: Yageo; Manufacturer_PN: RC0201FR-073K01L; Operating_Temp: -55°C ~ 125°C; Package: 0201; Part_Status: Unrel; Rating: 1/20W; Tolerance: 1%
R16 R20 R41 = RES: RES, 4.7K OHM, 5%, 1/20W, 0201; Approved: Approved; CY_PN: 500-60979-01; Device_File: 500-60979-01; FPLIST: RESC0603_0201N,RESC0603_0201Q; Lifecycle: Active; Manufacturer: Yageo; Manufacturer_PN: RC0201JR-074K7L; Operating_Temp: -55°C ~ 125°C; Package: 0201; Part_Status: Unrel; Rating: 1/20W; Tolerance: 5%
R279 = RES: RES, 15K OHM, 1%, 1/20W, 0201; Approved: Approved; CY_PN: 500-61327-01; Device File: 500-60868-01; Device_File: 500-61327-01; FPLIST: RESC0603_0201N,RESC0603_0201Q; Lifecycle: Active; Manufacturer: Yageo; Manufacturer_PN: RC0201FR-0715KL; NO_XNET_CONNECTION: YES; Operating_Temp: -55°C ~ 125°C; Package: 0201; Part_Status: Unrel; Rating: 1/20W; Tolerance: 1%
R280 = RES: RES, 30K OHM, 1%, 1/20W, 0201; Approved: Approved; CY_PN: 500-61325-01; Device File: 500-60558-01; Device_File: 500-61325-01; FPLIST: RESC0603_0201N,RESC0603_0201Q; Lifecycle: Active; Manufacturer: Yageo; Manufacturer_PN: RC0201FR-0730KL; NO_XNET_CONNECTION: YES; Operating_Temp: -55°C ~ 125°C; Package: 0201; Part_Status: Unrel; Rating: 1/20W; Tolerance: 1%
R73 R82 R283 R286 = RES: RES, Fixed, 0 OHM, JUMPER, 0.5A, 0201; CY_PN: 500-60684-01; DNI: DNI; Device File: 500-60037-01; Device_File: 500-60684-01; FPLIST: RESC0603_0201N,RESC0603_0201Q; Lifecycle: Active; Manufacturer: Yageo; Manufacturer_PN: RC0201JR-070RL; Operating_Temp: -55°C to 125°C; Package: 0201; Part_Status: In Production; Rating: 0.5A; Tolerance: JUMPER
R27 R290 = RES: RES, Fixed, 0 OHM, JUMPER, 1A, 0402; CY_PN: 500-60585-01; Device File: 500-60037-01; Device_File: 500-60585-01; FPLIST: RESC1005_0402N,RESC1005_0402M; Lifecycle: Active; Manufacturer: Yageo; Manufacturer_PN: RC0402JR-070RL; Operating_Temp: -55°C to 155°C; Package: 0402; Part_Status: In Production; Rating: 1A; Tolerance: JUMPER
R297 R298 = RES: RES, 30K OHM, 1%, 1/20W, 0201; Approved: Approved; CY_PN: 500-61325-01; DNI: DNI; Device_File: 500-61325-01; FPLIST: RESC0603_0201N,RESC0603_0201Q; Lifecycle: Active; Manufacturer: Yageo; Manufacturer_PN: RC0201FR-0730KL; Operating_Temp: -55°C ~ 125°C; Package: 0201; Part_Status: Unrel; Rating: 1/20W; Tolerance: 1%
TP1-TP9 TP30 TP32-TP34 = TP_SMD: TestPoint, PCB, Circle, 1mm, SMD; CY_PN: NA; DNI: DNI; Lifecycle: NA; Manufacturer: NA; Manufacturer_PN: NA; Part_Status: NA
U8 = IC_BQ24074_0: IC, REG, Battery Charger, Single Cell Li-Ion, 1.5A, 16VQFN; Approved: Approved; CY_PN: 471-60048-01; Device_File: 471-60048-01; Lifecycle: Active; Manufacturer: TI; Operating_Temp: -40°C ~ 125°C; Operating_Voltage: 4.35V ~ 10.2V; Package: VQFN 16; Part_Status: Unrel
U9 U16 = ESD5V3U2U-03F: DIO, INFINEON, ESD Protection, 5.3V, 2CH, +/-20KV, SOT-723; Approved: Approved; HARD_LOCATION: YES; Lifecycle: Active; Manufacturer: IFX; Operating_Temp: -40°C to 125°C; Package: SOT-723; Part_Status: Unrel; Rating: +/-20KV, 3A; Voltage: 5.3V
C9-C11 = CAP-NP: CAP, CER, 10uF, 20%, X5R, 10V, 0402; CY_PN: 510-60337-01; Device_File: 510-60337-01; Dielectric: X5R; FPLIST: CAPC1005_0402N,CAPC1005_0402M; Lifecycle: Active; Manufacturer: Samsung; Manufacturer_PN: CL05A106MP8NUB8; Operating_Temp: -55°C to 85°C; Package: 0402; Part_Status: In Prod; Tolerance: 20%; Voltage: 10V
C253 = CAP-NP: CAP, CER, 150pF, 5%, C0G/NP0, 50V, 0402; Approved: Approved; CY_PN: 510-60512-02; DNI: DNI; Device_File: 510-60512-02; Dielectric: C0G/NP0; FPLIST: CAPC1005_0402N,CAPC1005_0402M; Lifecycle: Active; Manufacturer: Samsung; Manufacturer_PN: CL05C151JB5NNNC; Operating_Temp: -55°C ~ 125°C; Package: 0402; Part_Status: In Prod; Tolerance: 5%; Voltage: 50V
L1 = IND: IND, FIXED, SHIELDED, 2.2uH, 20%, 1.7A, 0.050 OHM, SMD; Approved: Approved; CY_PN: 520-60318-01; Current: 1.7A; DB_Status: Verified; Device_File: 520-60318-01; ESR: 50mOHM; Lifecycle: Active; Manufacturer: Wurth; Manufacturer_PN: 74404032022; Material: shielded; Operating_Temp: -40°C ~ 85°C; Package: SMD; Part_Status: Unrel; Part_Type: Inductor; Tolerance: 20%
R19 R22 R25 = RES: RES, 4.7K OHM, 5%, 1/20W, 0201; Approved: Approved; CY_PN: 500-60979-01; Device File: 500-60075-01; Device_File: 500-60979-01; FPLIST: RESC0603_0201N,RESC0603_0201Q; Lifecycle: Active; Manufacturer: Yageo; Manufacturer_PN: RC0201JR-074K7L; Operating_Temp: -55°C ~ 125°C; Package: 0201; Part_Status: Unrel; Rating: 1/20W; Tolerance: 5%
R21 = RES: RES, 560K OHM, 1%, 1/20W, 0201; Approved: Approved; CY_PN: 500-61332-01; Device_File: 500-61332-01; FPLIST: RESC0603_0201N,RESC0603_0201Q; Lifecycle: Active; Manufacturer: Yageo; Manufacturer_PN: RC0201FR-07560KL; Operating_Temp: -55°C ~ 125°C; Package: 0201; Part_Status: Unrel; Rating: 1/20W; Tolerance: 1%
R23 = RES: RES, 90.9K OHM, 1%, 1/20W, 0201; Approved: Approved; CY_PN: 500-61331-01; Device_File: 500-61331-01; FPLIST: RESC0603_0201N,RESC0603_0201Q; Lifecycle: Active; Manufacturer: Yageo; Manufacturer_PN: RC0201FR-0790K9L; Operating_Temp: -55°C ~ 125°C; Package: 0201; Part_Status: Unrel; Rating: 1/20W; Tolerance: 1%
R24 = RES: RES, 4.7K OHM, 5%, 1/20W, 0201; Approved: Approved; CY_PN: 500-60979-01; DNI: DNI; Device File: 500-60075-01; Device_File: 500-60979-01; FPLIST: RESC0603_0201N,RESC0603_0201Q; Lifecycle: Active; Manufacturer: Yageo; Manufacturer_PN: RC0201JR-074K7L; Operating_Temp: -55°C ~ 125°C; Package: 0201; Part_Status: Unrel; Rating: 1/20W; Tolerance: 5%
U11 = IC_RT6150B_0: IC, REG, BUCK BST, ADJ, 800MA, 10WDFN; Approved: Approved; CY_PN: 470-60022-01; Device_File: 470-60022-01; Lifecycle: Active; Manufacturer: Richtek; Operating_Temp: -40°C ~ 85°C (TA); Operating_Voltage: 1.8V - 5.5V; Package: 10WDFN; Part_Status: Unrel
U20 = IC_NCP115AMX_0: IC, REG, LINEAR, 3.3V, 300mA, 4XDFN; Approved: Approved; CY_PN: 471-60050-01; Device_File: 471-60050-01; Lifecycle: Active; Manufacturer: ONSEMI; Operating_Temp: -40°C ~ 85°C; Operating_Voltage: 3.3V; Package: 4XDFN; Part_Status: Unrel
U21 = IC_NCP115AMX_0: IC, REG, LINEAR, 1.8.V, 300mA, 4XDFN; Approved: Approved; CY_PN: 471-60051-01; Device_File: 471-60051-01; Lifecycle: Active; Manufacturer: ONSEMI; Operating_Temp: -40°C ~ 85°C; Operating_Voltage: 1.8V; Package: 4XDFN; Part_Status: Unrel
C16 C18 C20 C22 C24 C25 C27 C29 C31 C33 C34 C56 = CAP-NP: CAP, CER, 1UF, 10V, X5R, 0201; Approved: Approved; CY_PN: 510-61118-01; Device File: 510-60276-01; Device_File: 510-61118-01; Dielectric: X5R; FPLIST: CAPC0603_0201N,CAPC0603_0201Q; Lifecycle: Active; Manufacturer: YAEGO; Manufacturer_PN: CC0201MRX5R6BB105; Operating_Temp: -55°C ~ 85°C; Package: 0201; Part Status: In Prod; Part_Status: In Prod; Tolerance: 20%; Voltage: 10V
C17 C19 C21 C23 C26 C28 C30 C32 C57 C58 = CAP-NP: CAP, CER, 0.1uF, 20%, X5R, 10V, 0201; Approved: Approved; CY_PN: 510-60777-01; Device File: 510-60330-01; Device_File: 510-60777-01; Dielectric: X5R; FPLIST: CAPC0603_0201N,CAPC0603_0201Q; Lifecycle: Active; Manufacturer: Wurth; Manufacturer_PN: 885012104002; Operating_Temp: -55°C ~ 85°C; Package: 0201; Part Status: In Prod; Part_Status: In Prod; Tolerance: 20%; Voltage: 10V
R28 = RES: RES, 49.9K OHM, 1%, 1/20W, 0201; Approved: Approved; CY_PN: 500-61326-01; Device File: 500-60149-01; Device_File: 500-61326-01; FPLIST: RESC0603_0201N,RESC0603_0201Q; Lifecycle: Active; Manufacturer: Yageo; Manufacturer_PN: RC0201FR-0749K9L; Operating_Temp: -55°C ~ 125°C; Package: 0201; Part_Status: Unrel; Rating: 1/20W; Tolerance: 1%
R29 = RES: RES, 49.9K OHM, 1%, 1/20W, 0201; Approved: Approved; CY_PN: 500-61326-01; DNI: DNI; Device File: 500-60149-01; Device_File: 500-61326-01; FPLIST: RESC0603_0201N,RESC0603_0201Q; Lifecycle: Active; Manufacturer: Yageo; Manufacturer_PN: RC0201FR-0749K9L; Operating_Temp: -55°C ~ 125°C; Package: 0201; Part_Status: Unrel; Rating: 1/20W; Tolerance: 1%
R30 R33 = RES: RES, 15K OHM, 1%, 1/20W, 0201; Approved: Approved; CY_PN: 500-61327-01; Device File: 500-60868-01; Device_File: 500-61327-01; FPLIST: RESC0603_0201N,RESC0603_0201Q; Lifecycle: Active; Manufacturer: Yageo; Manufacturer_PN: RC0201FR-0715KL; Operating_Temp: -55°C ~ 125°C; Package: 0201; Part_Status: Unrel; Rating: 1/20W; Tolerance: 1%
R31 R36 = RES: RES, 30K OHM, 1%, 1/20W, 0201; Approved: Approved; CY_PN: 500-61325-01; Device File: 500-60558-01; Device_File: 500-61325-01; FPLIST: RESC0603_0201N,RESC0603_0201Q; Lifecycle: Active; Manufacturer: Yageo; Manufacturer_PN: RC0201FR-0730KL; Operating_Temp: -55°C ~ 125°C; Package: 0201; Part_Status: Unrel; Rating: 1/20W; Tolerance: 1%
R34 R281 R282 = RES: RES, 4.7K OHM, 5%, 1/20W, 0201; Approved: Approved; CY_PN: 500-60979-01; Device File: 500-60095-01; Device_File: 500-60979-01; FPLIST: RESC0603_0201N,RESC0603_0201Q; Lifecycle: Active; Manufacturer: Yageo; Manufacturer_PN: RC0201JR-074K7L; Operating_Temp: -55°C ~ 125°C; Package: 0201; Part_Status: Unrel; Rating: 1/20W; Tolerance: 5%
R35 R37 = RES: RES, 22 OHM, 5%, 1/20W, 0201; Approved: Approved; CY_PN: 500-61328-01; Device File: 500-60085-01; Device_File: 500-61328-01; FPLIST: RESC0603_0201N,RESC0603_0201Q; Lifecycle: Active; Manufacturer: Yageo; Manufacturer_PN: RC0201JR-0722RL; Operating_Temp: -55°C ~ 125°C; Package: 0201; Part_Status: Unrel; Rating: 1/20W; Tolerance: 5%
R38 = RES: RES, 560 OHM, 5%, 1/20W, 0201; Approved: Approved; CY_PN: 500-61330-01; Device_File: 500-61330-01; FPLIST: RESC0603_0201N,RESC0603_0201Q; Lifecycle: Active; Manufacturer: Yageo; Manufacturer_PN: RC0201JR-07560RL; Operating_Temp: -55°C ~ 125°C; Package: 0201; Part_Status: Unrel; Rating: 1/20W; Tolerance: 5%
R64 R65 R72 R74 R80 R81 R285 R287 R295 R296 = RES: RES, Fixed, 0 OHM, JUMPER, 0.5A, 0201; CY_PN: 500-60684-01; Device File: 500-60037-01; Device_File: 500-60684-01; FPLIST: RESC0603_0201N,RESC0603_0201Q; Lifecycle: Active; Manufacturer: Yageo; Manufacturer_PN: RC0201JR-070RL; Operating_Temp: -55°C to 125°C; Package: 0201; Part_Status: In Production; Rating: 0.5A; Tolerance: JUMPER
SW1-SW3 = SWITCH-PB-12-34-G56: SW, Tactile Switch SPST-NO, TOP Actuated SMD; Actuator_Length: 0.4mm; Approved: Approved; CY_PN: 770-60161-01; Circuit: SPST-NO; Current_Rating: 0.05A; Lifecycle: Active; Manufacturer: Wurth; Operating_Force: 160gf; Operating_Temp: -40°C ~ 85°C; Part_Status: Unrel; Pins: 6; Switch_Function: Off-Mom
U2 = CY8C5868LTI-LP039: IC, CYPRESS, MCU, PSoC 5LP, 32 Bit MCU, 67MHz, 1.8V-5.5V, 68-QFN; Description1: 64KB SRAM, 256KB Flash, 2KB EEPROM, 20-bit Del-Sig, 2x12-bit SAR, 24UDBs, FS USB, CAN, 38 GPIO, 8 SIO; FPLIST: QFN40P800X800X100-69M,QFN40P800X800_68-H580N; Lifecycle: Active; Manufacturer: Cypress; Operating_Temp: -40°C to 85°C; Operating_Voltage: 1.8V-5.5V; Package: 68-QFN; Part_Status: In Prod
C60 C61 = CAP-NP: CAP, CER, 22pF, 5%, NP0, 25V, 0201; Approved: Approved; CY_PN: 510-60833-01; Description1: `; Device_File: 510-60833-01; Dielectric: NP0; FPLIST: CAPC0603_0201N,CAPC0603_0201Q; Lifecycle: Active; Manufacturer: Wurth; Manufacturer_PN: 885012004008; Operating_Temp: - 55 C to + 125 C; Package: 0201; Part_Status: In Prod; Tolerance: 5%; Voltage: 25V
C62 C63 = CAP-NP: CAP, CER, 10pF, 5%, NP0, 25V, 0201; Approved: Approved; CY_PN: 510-60782-01; Device_File: 510-60782-01; Dielectric: NP0; FPLIST: CAPC0603_0201N,CAPC0603_0201Q; Lifecycle: Active; Manufacturer: Wurth; Manufacturer_PN: 885012004004; Operating_Temp: - 55 C to + 125 C; Package: 0201; Part_Status: In Prod; Tolerance: 5%; Voltage: 25V
D9 = DIO-TVS: DIO, TVS, UNIDIR, 5V, 18.6V, 174W, SOD-523; CY_PN: 530-60165-01; Device File: 530-60165-01; Device_File: 530-60165-01; Lifecycle: Active; Manufacturer: MCC; Operating_Temp: -55°C to 150°C; Package: SOD-523; Part_Status: In Prod; Rating: 174W; Voltage: 5V
J4 = PLG-10-ODD-EVEN-J: CONN, HDR, MALE, DUAL, 10POS, 1.27mm, GOLD, STR, SMD; CY_PN: 710-60030-01; Conatct_Length: 3.05mm; Contact_Finish: GOLD; Current_Rating: 3.4A; Device_File: 710-60030-01; Lifecycle: Active; Manufacturer: Samtec; Manufacturer_PN: FTSH-105-01-L-DV-K-P-TR; Mated_Height: 5.97mm; Operating_Temp: -55°C to 125°C; Part_Status: In Prod; Pin_Pitch: 1.27; Pins: 10; Row_pitch: 1.27; Rows: 2; Shrouding: Shrouded
Y1 = XTAL-2P: XTAL, 32.768kHz, 20ppm, 12.5pF, SMD; Approved: Approved; CY_PN: 542-60119-01; Device_File: 542-60119-01; Lifecycle: Active; Load_Capacitance: 12.5pF; Manufacturer: WURTH; Manufacturer_PN: 830065253; Operating_Temp: -55°C ~ 125°C; Output_Type: NA; Package: SMD; Part_Status: Unrel; Supply_Voltage: NA; Tolerance: 20ppm
Y2 = XTAL-4P-2G4G: CRYSTAL, 24MHZ, ±10ppm, 10PF, SMD; Approved: Approved; CY_PN: 542-60117-01; Device_File: 542-60117-01; Frequency_Stability: 15ppm; Lifecycle: Active; Load_Capacitance: 10PF; Manufacturer: CTS; Manufacturer_PN: 402F2401XIAR; Operating_Temp: -40°C ~ 105°C; Output_Type: NA; Package: SMD; Part_Status: Unrel; Supply_Voltage: NA; Tolerance: 10ppm
C245 = CAP-NP: CAP CER 2.2UF 10V X5R 0402; Approved: Approved; CY_PN: 510-60376-01; Device_File: 510-60376-01; Dielectric: X5R; FPLIST: CAPC1005_0402N,CAPC1005_0402M; Lifecycle: Active; Manufacturer: Wurth; Manufacturer_PN: 885012105013; Operating_Temp: -55°C ~ 85°C; Package: 0402; Part_Status: In Prod; Tolerance: 20%; Voltage: 10V
R66 = RES: RES, 100K OHM, 1%, 1/20W, 0201; Approved: Approved; CY_PN: 500-61334-01; DNI: DNI; Device File: 500-60429-01; Device_File: 500-61334-01; FPLIST: RESC0603_0201N,RESC0603_0201Q; Lifecycle: Active; Manufacturer: Yageo; Manufacturer_PN: RC0201FR-07100KL; Operating_Temp: -55°C ~ 125°C; Package: 0201; Part_Status: Unrel; Rating: 1/20W; Tolerance: 1%
R71 R79 = RES: RES, FIXED, 100 OHM, 5%, 1/20W, 0201; Approved: Approved; CY_PN: 500-61324-01; Device File: 500-60384-01; Device_File: 500-61324-01; FPLIST: RESC0603_0201N,RESC0603_0201Q; Lifecycle: Active; Manufacturer: Yageo; Manufacturer_PN: RC0201JR-07100RL; Operating_Temp: -55°C ~ 125°C; Package: 0201; Part_Status: Unrel; Rating: 1/20W; Tolerance: 5%
U3 = IC_DPS368: IC, INFINEON, SENSOR, 17.4PSIG, 24BIT, 8VLGA; Approved: Approved; Lifecycle: Active; Manufacturer: infineon; Operating_Temp: -40°C ~ 85°C; Operating_Voltage: 1.7V ~ 3.6V; Package: 8VLGA; Part_Status: Unrel
U4 U5 = IC_IM72D128V01_4: IC, INFINEON, DIGITAL MEMS MICROPHONE, 1.62 to 3.6V, -36dB, SMD; Approved: Approved; Lifecycle: Active; Manufacturer: Infineon; Operating_Temp: -40°C ~ 85°C; Operating_Voltage: 1.62 V ~ 3.6 V; Package: SMD; Part_Status: Unrel
U18 = IC_BMI270: IC, IMU, ACCELEROMETER/GYRO, 6-AXIS, I2C/SPI, 14-LGA; Approved: Approved; CY_PN: 415-00031-01; Device_File: 415-00031-01; Lifecycle: Active; Manufacturer: Bosch; Operating_Temp: -40°C to 85°C; Operating_Voltage: 1.71V~3.6V, 1.2V~3.6V; Package: 14-LGA; Part_Status: Unrel
U19 = IC_BMM350: IC, SENSOR, MAGNETOMETER, MAGNETORESISTIVE, 3-AXIS, I2C/I3C, 9-WLCSP; Approved: Approved; CY_PN: 415-00032-01; Device_File: 415-00032-01; Lifecycle: Active; Manufacturer: Bosch; Operating_Temp: -40°C to 85°C; Operating_Voltage: 1.72V~1.98V, 1.72V~3.6V; Package: 9-WLCSP; Part_Status: Unrel

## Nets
GND_EARTH: C6.1 J1.SH1 J1.SH2 J1.SH3 J1.SH4 J2.SH1 J2.SH2 J2.SH3 J2.SH4 R7.1
GND_SIGNAL: C1.2 C2.2 C3.2 C4.2 C5.2 C6.2 C7.2 C8.2 C9.2 C10.2 C11.2 C12.2 C13.2 C14.2 C15.2 C16.2 C17.2 C18.2 C19.2 C20.2 C21.2 C22.2 C23.2 C24.2 C25.2 C26.2 C27.2 C28.2 C29.2 C30.2 C31.2 C32.2 C33.2 C34.2 C56.2 C57.2 C58.2 C60.1 C61.1 C62.2 C63.2 C66.2 C67.2 C68.2 C71.2 C115.2 C116.1 C119.2 C121.2 C245.2 C256.2 D1.K(CATHODE) D2.K(CATHODE) D3.K(CATHODE) D4.A(ANODE) D9.A(ANODE) D10.A(ANODE) D12.K(CATHODE) J1.A1(GND_1) J1.A12(GND_2) J1.B1(GND_3) J1.B12(GND_4) J2.A1(GND_1) J2.A12(GND_2) J2.B1(GND_3) J2.B12(GND_4) J3.2 J3.SH1 J3.SH2 J4.3 J4.5 J4.7 J4.9 R5.2 R6.2 R7.2 R8.1 R9.1 R10.1 R11.1 R12.1 R14.2 R15.2 R16.2 R17.2 R18.2 R23.2 R24.2 R29.1 R31.1 R36.1 R55.1 R66.2 R74.2 R82.2 R101.2 R102.2 R280.1 R287.2 SW1.3 SW1.4 SW1.5(GND) SW1.6(GND) SW2.5(GND) SW2.6(GND) SW3.3 SW3.4 SW3.5(GND) SW3.6(GND) TP2.1(TP) TP4.1(TP) TP6.1(TP) U2.5(VSSB) U2.7(VBOOST) U2.8(VBAT) U2.9(VSSD) U2.25(VSSD) U2.43(VSSA) U2.45(VSSD) U2.58(VSSD) U2.62(P2[0]) U2.63(P2[1]) U2.H(EPAD) U3.1(GND) U3.7(GND) U4.5(GND) U5.5(GND) U8.8(VSS) U8.H(EPAD) U9.3(GND) U11.3(GND_1) U11.9(GND_2) U11.H(GND_EPAD) U16.3(GND) U18.6(GNDIO) U18.7(GND) U19.B1(GND) U19.C3(BYPASS) U20.2(GND) U20.5(EPAD) U21.2(GND) U21.5(EPAD) Y2.2(GND_1) Y2.4(GND_2) ; also on sheet 9 10 11 13
VBAT_IN: C5.1 J3.1 TP34.1(TP) U8.2(BAT_1) U8.3(BAT_2)
VBUS_IN: C3.1 C4.1 D5.K D6.K R3.2 R4.2 R13.2 TP30.1(TP) U8.13(IN)
VCC_1V8: C15.1 C119.1 U19.C1(VDD) U21.1(OUT) ; also on sheet 9 10 11 13
VCC_3V3: C12.1 C66.1 C67.1 C68.1 C71.1 C115.1 C116.2 C121.1 R73.1 R81.1 R285.2 R286.2 U3.6(VDDIO) U3.8(VDD) U4.2(VDD) U5.2(VDD) U18.5(VDDIO) U18.8(VDD) U19.B2(ADSEL) U19.B3(VDDIO) U20.1(OUT) ; also on sheet 9 11 13
VCC_3V6: C7.1 C8.1 C10.1 C11.1 C13.1 C14.1 C253.1 C256.1 R19.1 R21.1 R25.1 R26.1 TP32.1(TP) U11.1(VOUT) U20.4(IN) U21.4(IN) ; also on sheet 10
VDDD: R41.1 ; also on sheet 13
VIN: C9.1 R20.1 R22.1 R290.1 TP33.1(TP) U11.5(VIN) U11.8(VINA)
ECO_XTAL_IN_P12_6: C62.1 Y2.1 ; also on sheet 14
ECO_XTAL_OUT_P12_7: C63.1 Y2.3 ; also on sheet 14
I2C_SCL_P0_2: R64.2 R282.1 R296.2 U18.13(SCX) U19.A3(SCK) ; also on sheet 11 14
I2C_SDA_P0_3: R65.2 R281.1 R295.2 U18.14(SDX) U19.A2(SDA) ; also on sheet 11 14
IMU_INT1_P1_5: U18.4(INT1) ; also on sheet 14
IMU_INT2_P0_4: U18.9(INT2) ; also on sheet 14
KP_UART_RX_P5_1: R34.1 U2.21(P12[7]) ; also on sheet 14
KP_UART_TX_P5_0: U2.20(P12[6]) ; also on sheet 14
KP_USB_DM: J1.A7(DN1) J1.B7(DN2) R37.1 U16.1(IN1)
KP_USB_DP: J1.A6(DP1) J1.B6(DP2) R35.1 U16.2(IN2)
KP_VBUS: D5.A D10.K(CATHODE) J1.A4(VBUS_1) J1.A9(VBUS_2) J1.B4(VBUS_3) J1.B9(VBUS_4) R27.2 R101.1 TP1.1(TP)
LBCPP_CE_n_P5_7: R10.2 U8.4(~{CE}) ; also on sheet 14
LBCPP_CHG_n_P5_6: R298.1 ; also on sheet 14
LBCPP_EN1_P6_1: R3.1 R11.2 U8.6(EN1) ; also on sheet 14
LBCPP_EN2_P6_0: R4.1 R12.2 U8.5(EN2) ; also on sheet 14
LBCPP_ITERM_P6_3: R283.2 ; also on sheet 14
LBCPP_PG_n_P5_5: R297.1 ; also on sheet 14
MAG_INT_P1_0: U19.A1(INT) ; also on sheet 14
P5LP1_2: SW3.1 SW3.2 U2.13(P1[2])
P5LP1_4: R38.2 U2.15(P1[4])
P5LP2_2: U2.64(P2[2])
P5LP2_3: U2.65(P2[3])
P5LP2_4: U2.66(P2[4])
P5LP_SIO_VREF: R28.2 R29.2 U2.48(P0[0])
P5LP_SWCLK: TP8.1(TP) U2.12(P1[1])
P5LP_SWDIO: TP9.1(TP) U2.11(P1[0])
P5LP_VCCD: C25.1 C26.1 U2.26(VCCD) U2.57(VCCD)
P5LP_VDD: C16.1 C17.1 C18.1 C19.1 C20.1 C21.1 C22.1 C23.1 C27.1 C28.1 C29.1 C30.1 C31.1 C32.1 R27.1 R33.1 TP5.1(TP) U2.17(VDDIO1) U2.24(VDDD) U2.35(VDDIO3) U2.44(VDDA) U2.52(VDDIO) U2.59(VDDD) U2.67(VDDIO2)
P5LP_XRES: TP7.1(TP) U2.10(~{XRES})
P6_RESET_L: C57.1 J4.10 R41.2 SW1.1 SW1.2 U2.3(P12[4]) ; also on sheet 14
P6_SWCLK_P6_7: J4.4 U2.47(P12[3]) ; also on sheet 14
P6_SWDIO_P6_6: J4.2 U2.46(P12[2]) ; also on sheet 14
P6_SWO_P6_4: J4.6 ; also on sheet 14
P6_TDI_P6_5: J4.8 ; also on sheet 14
P6_USB_DM: J2.A7(DN1) J2.B7(DN2) U9.1(IN1) ; also on sheet 14
P6_USB_DP: J2.A6(DP1) J2.B6(DP2) U9.2(IN2) ; also on sheet 14
P6_USB_S_P6_2: R279.2 R280.2 ; also on sheet 14
P6_VBUS: D4.K(CATHODE) D6.A J2.A4(VBUS_1) J2.A9(VBUS_2) J2.B4(VBUS_3) J2.B9(VBUS_4) R102.1 R279.1 TP3.1(TP)
P6_VTARG: C56.1 D9.K(CATHODE) J4.1 R28.1 R30.1 R34.2 R281.2 R282.2 ; also on sheet 13
PDM_CLK_P10_4: R72.2 R80.2 ; also on sheet 14
PDM_DATA_P10_5: R71.2 R79.2 ; also on sheet 14
PSEN_INT_P1_4: R66.1 U3.5(SDO) ; also on sheet 14
USB_V_SENSE: R33.2 R36.2 U2.19(P1[7])
USER_BTN_P5_2: C58.1 SW2.1 SW2.2 ; also on sheet 14
USER_LED1_P5_3: R62.2 ; also on sheet 14
USER_LED2_P5_4: R63.2 ; also on sheet 14
VTARG_MEAS: R30.2 R31.2 U2.32(P3[3])
WCO_XTAL_IN_P0_0: C60.2 Y1.2 ; also on sheet 14
WCO_XTAL_OUT_P0_1: C61.2 Y1.1 ; also on sheet 14
N17278110: R19.2 U20.3(EN)
N17278725: R64.1 U3.4(SCK)
N17278748: R65.1 U3.3(SDI)
N17279219: R73.2 R74.1 U4.4(SELECT)
N17279342: R81.2 R82.1 U5.4(SELECT)
N17363073: J1.A5(CC1) R6.1
N17363075: J1.B5(CC2) R5.1
N17373677: J2.A5(CC1) R18.1
N17373681: J2.B5(CC2) R17.1
N17374662: D8.K(CATHODE) R297.2 U8.7(~{PGOOD})
N17374666: D8.A(ANODE) R1.1
N17374668: C1.1 C2.1 R1.2 R2.2 R290.2 U8.10(OUT_1) U8.11(OUT_2)
N17374688: D11.K(CATHODE) R298.2 U8.9(~{CHG})
N17374692: D11.A(ANODE) R2.1
N17374847: R8.2 U8.1(TS)
N17374885: R9.2 U8.14(TMR)
N17374979: R13.1 R14.1 R283.1 U8.15(ITERM)
N17374981: R15.1 U8.12(ILIM)
N17374983: R16.1 U8.16(ISET)
N17378355: C253.2 R21.2 R23.1 U11.10(FB)
N17378650: D1.A(ANODE) R26.2
N17390542: R25.2 U21.3(EN)
N17393871: L1.1 U11.2(LX2)
N17393876: L1.2 U11.4(LX1)
N17394939: R20.2 U11.6(EN)
N17395527: R22.2 R24.1 U11.7(PS)
N17444411: C245.1 U19.C2(CRST)
N17489317: R55.2 SW2.3 SW2.4
N17489457: D2.A(ANODE) R62.1
N17489487: D3.A(ANODE) R63.1
N17506574: R285.1 U18.12(CSB)
N17506591: R286.1 R287.1 U18.1(SDO)
N17580471: C24.1 U2.53(P0[4])
N17581080: C33.1 U2.42(VCCA)
N17581130: R35.2 U2.22(P15[6]_D+)
N17581131: R37.2 U2.23(P15[7]_D-)
N17581135: C34.1 U2.31(P3[2])
N17595911: R295.1 U2.39(P12[1])
N17595914: R296.1 U2.38(P12[0])
N17606878: D12.A(ANODE) R38.1
N17666742: R71.1 U4.1(DATA)
N17666744: R72.1 U4.3(CLOCK)
N17666957: R79.1 U5.1(DATA)
N17666958: R80.1 U5.3(CLOCK)

Not connected (* = marked no-connect by the designer): J1 A8(SBU1)* B8(SBU2)*; J2 A8(SBU1)* B8(SBU2)*; U2 1(P2[6])* 2(P2[7])* 4(P12[5])* 6(IND)* 14(P1[3])* 16(P1[5])* 18(P1[6])* 27(P15[0])* 28(P15[1])* 29(P3[0])* 30(P3[1])* 33(P3[4])* 34(P3[5])* 36(P3[6])* 37(P3[7])* 40(P15[2])* 41(P15[3])* 49(P0[1])* 50(P0[2])* 51(P0[3])* 54(P0[5])* 55(P0[6])* 56(P0[7])* 60(P15[4])* 61(P15[5])* 68(P2[5])*; U3 2(CSB)*; U18 2(ASDx)* 3(ASCx)* 10(OCSB)* 11(OSDO)*

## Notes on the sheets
sheet 1
- CY8CKIT-062S2-AI PSoC™ 6 AI Evaluation Board
- CONTENTS
- PAGE
- DESCRIPTION
- 01
- Title, Table of Contents & Drawing Numbers
- 02
- Function Block Diagram
- 03
- Power Block Diagram
- 04
- USB and Battery Power Supply
- 05
- Regulated Voltage Supply
- 06
- KitProg3 Interface
- 07
- PSoC™ 6 Power
- 08
- PSoC™ 6 Signals
- 09
- On-board Peripherals
- 10
- Sensors and Accessories
- 11
- QSPI Memory and RADAR Interface
- 12
- WiFi / BLE Module Interface
- 13
- Addon board interface
- 14
- Revision History
- Drawing Numbers
- PCBA
- PCB
- FAB DRW
- ASSY DRW
- SCH DRW
sheet 4
- KitProg3 USB Interface and Power Supply
- Li-ion Battery Charger and Power path
- GREEN
- RED
- PSoC™ 6 USB Device Interface and Power Supply
- EN2
- EN1
- Maximum Input Current
- 0         0        100mA, USB100 mode
- NOTE:
- 0         1        500mA, USB500 mode
- ISET: Charge current set to
  190mA approx
  ILIM: Input current limit set
  to1.6A approx
- 1         0        Set by ILIM resistor
- 1         1        USB Suspend mode
- Power Supply  Or'ing
- Li-ion Battery
  Connector
sheet 5
- Buck-Boost Power supply
- 3.3V Power supply
- 1.8V Power supply
- Power LED
- RED
sheet 6
- Decoupling Capacitors
- PSoC™ 5LP based KitProg3
- PSoC™ 5LP Power
- SAR Bypass
  Capacitor
- Voltage Monitoring
- PSoC™ 5LP Programming Header
- Note:
- This is used for programing on board PSoC™ 5LP
  with KitProg3 firmware
- KitProg3 UART RX Pull Up
- Del-Sig Bypass Capacitor
- KitProg3 H/W Revision
- KitProg3 Mode Switch
- KitProg3 Status LED
- I2C Pull Ups
- Bit 0
- Bit 1
- Bit 2
- RED
- Bit 3
- Bit 4
- ID = 0x03
- GND is read as binary "1" and
  floating as "0"
- Note:
sheet 7
- Digital Barometric Pressure Sensor
- 6-axis IMU (Accelerometer + Gyroscope)
- NOTE:
- R66 is open I2C address
  is 0x77, if loaded then
  0x76
- Digital MEMS Microphone 1
- NOTE:
- If SDO=0, I2C address is 0x68 (Default)
  If SDO=1, I2C address is 0x69
- 3-axis Magnetometer
- NOTE:
- PDM DATA is available on
  Logic LOW of Clock signal
- Digital MEMS Microphone 2
- NOTE:
- I2C Slave Address: 0x15
- NOTE:
- PDM DATA is available on
  Logic HIGH of Clock signal
sheet 8
- PSoC™ 6 ECO Source
- PSoC™ 6 WCO Source
- PSoC™ 6 SWD/JTAG Header
- TMS/SWDIO
- TCK/SWCLK
- TDO/SWO
- TDI
- XRES
- User LED's
- Reset Switch
- User Button
- RED
- RED
